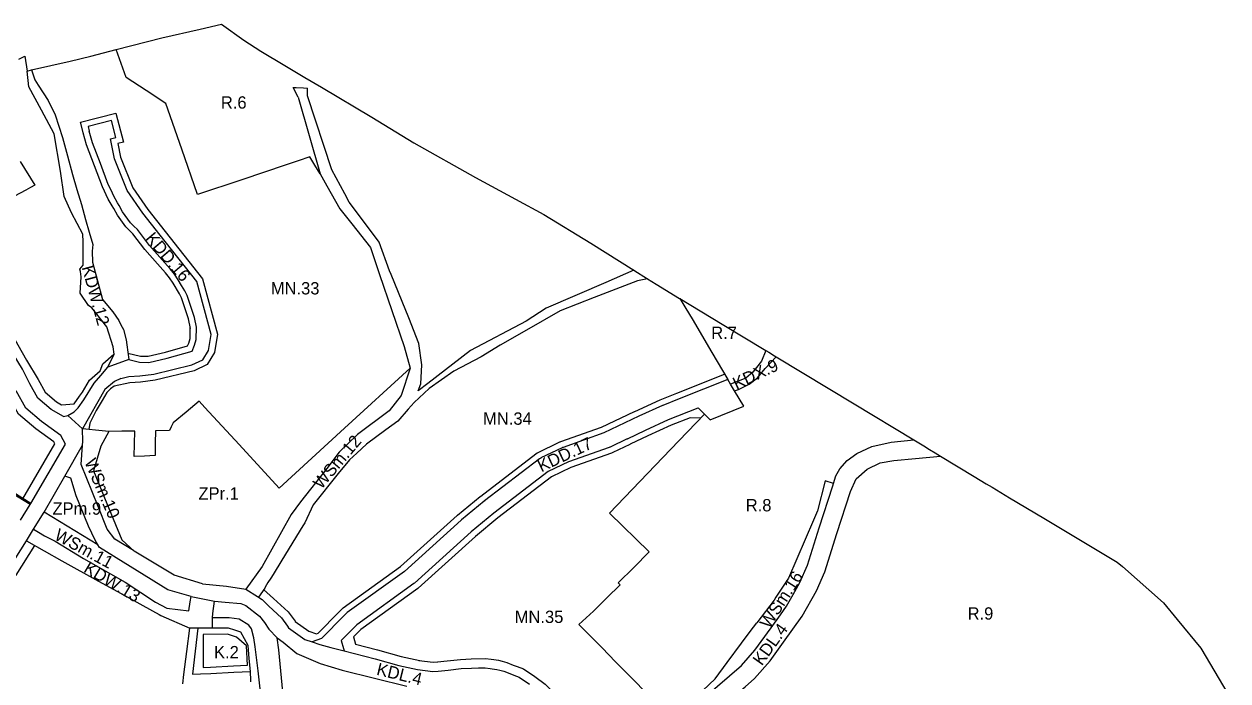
# Model space of a CAD drawing. Extents: x 7431080 to 7433370, y 5546450 to 5548428.
# Drawn here: x 7432562 to 7433342, y 5547508 to 5547934 of the extents above; entities that cross this region are included whole.
import ezdxf

# ---------------------------------------------------------------- set-up
doc = ezdxf.new("R2010")
doc.units = 0
for name, color, linetype in [('Linie Rozgraniczajace', 7, 'Continuous'), ('nieprzekraczalna linia zabudowy', 7, 'Continuous'), ('oznaczenia_przeznaczen', 7, 'Continuous')]:
    doc.layers.add(name, color=color, linetype=linetype)

msp = doc.modelspace()

# ---------------------------------------------------------------- linework, layer by layer
at = {"layer": 'Linie Rozgraniczajace'}
for p, q in [((7432736.74, 5547893.15), (7432738.64, 5547893.31)), ((7432739.88, 5547887.05), (7432736.74, 5547893.15)), ((7432738.64, 5547893.31), (7432743.31, 5547893.03)), ((7432743.31, 5547893.03), (7432745.96, 5547892.87)), ((7432745.83, 5547887.8), (7432745.96, 5547892.87)), ((7432630.14, 5547716.75), (7432616.64, 5547711.94)), ((7433018.29, 5547703.96), (7432986.81, 5547691.39)), ((7432600.23, 5547671.83), (7432590.53, 5547680.61)), ((7432670.6, 5547563.08), (7432685.71, 5547560.16)), ((7432674.84, 5547542.6), (7432669.79, 5547542.58)), ((7432830.69, 5547514.77), (7432837.12, 5547515.42)), ((7432837.12, 5547515.42), (7432845.5, 5547516.43)), ((7432845.5, 5547516.43), (7432852.26, 5547516.8)), ((7432852.26, 5547516.8), (7432856.77, 5547516.88)), ((7432856.77, 5547516.88), (7432861.06, 5547516.96)), ((7432861.06, 5547516.96), (7432864.23, 5547516.59)), ((7432864.23, 5547516.59), (7432865.68, 5547516.37)), ((7432865.68, 5547516.37), (7432868.53, 5547515.91)), ((7432868.53, 5547515.91), (7432870.64, 5547515.46)), ((7432870.64, 5547515.46), (7432873.14, 5547514.79)), ((7432873.14, 5547514.79), (7432876.99, 5547513.17)), ((7432876.99, 5547513.17), (7432879.7, 5547512.14)), ((7432709.13, 5547507.75), (7432709.11, 5547508.64)), ((7432879.7, 5547512.14), (7432883.07, 5547510.87)), ((7432883.07, 5547510.87), (7432889.86, 5547506.34)), ((7432982.62, 5547483.83), (7433010.04, 5547509.76))]:
    msp.add_line(p, q, dxfattribs=at)
for points in [[(7432558.92, 5547911.54), (7432562.86, 5547913.51), (7432564.19, 5547903.89), (7432567.09, 5547904.65), (7432592.1, 5547910.39), (7432605.56, 5547913.52), (7432622.02, 5547917.81), (7432651.51, 5547925.34), (7432676.39, 5547931.16), (7432690.27, 5547934.37), (7432704.62, 5547923.9), (7432715.72, 5547916.75), (7432731.3, 5547907.41), (7432744.28, 5547899.66), (7432755, 5547893.51), (7432787.72, 5547873.89), (7432814.91, 5547857.43), (7432854.84, 5547834.94), (7432880.76, 5547820.75), (7432899.09, 5547810.91), (7432929.43, 5547792.22), (7432957.36, 5547774.72), (7432966.22, 5547769.17), (7432971.79, 5547765.66), (7432987, 5547756.47), (7432987.09, 5547756.42), (7433014.57, 5547739.79), (7433042.93, 5547722.68), (7433044.83, 5547721.53), (7433048.58, 5547719.26), (7433049.72, 5547718.57), (7433100.18, 5547688.13), (7433138.81, 5547664.71), (7433145.3, 5547660.77), (7433148.91, 5547658.58), (7433152.72, 5547656.27), (7433156.12, 5547654.21), (7433178, 5547640.94), (7433185.69, 5547636.29), (7433189.55, 5547633.97), (7433200.87, 5547627.21), (7433223.05, 5547613.95), (7433248.93, 5547598.46), (7433270.56, 5547585.53), (7433273.96, 5547582.54), (7433300.55, 5547559.07), (7433309.47, 5547548.27), (7433324.78, 5547529.73), (7433342.34, 5547500)], [(7432654.21, 5547882.91), (7432641.32, 5547891.34), (7432628.43, 5547899.76), (7432625.23, 5547908.79), (7432622.02, 5547917.81)], [(7432587.74, 5547679.83), (7432590.53, 5547680.61), (7432594.68, 5547682.98), (7432597.33, 5547685.52), (7432601.04, 5547690.78), (7432607.78, 5547701.42), (7432611.99, 5547706.44), (7432616.64, 5547711.94), (7432620.59, 5547720.23), (7432620.03, 5547724.97), (7432615.88, 5547738.05), (7432606.1, 5547750.39), (7432604.04, 5547751.77), (7432598.65, 5547759.97), (7432599.38, 5547770.41), (7432598.77, 5547773.94), (7432598.49, 5547775.52), (7432600.47, 5547778.02), (7432600.49, 5547779.73), (7432600.67, 5547793.18), (7432600.35, 5547798.04), (7432592.99, 5547811.92), (7432588.3, 5547822.61), (7432585.93, 5547839.01), (7432581.86, 5547863.28), (7432573.58, 5547878.52), (7432565.31, 5547893.76), (7432564.19, 5547903.89)], [(7432567.09, 5547904.65), (7432569.35, 5547898.3), (7432571.48, 5547894.68), (7432577.93, 5547884.8), (7432582.51, 5547875.58), (7432584.86, 5547868.23), (7432587.2, 5547860.87), (7432590.45, 5547848.87), (7432593.69, 5547836.86), (7432596.55, 5547827.15), (7432599.41, 5547817.43), (7432602.14, 5547807.71), (7432604.45, 5547799.52), (7432606.75, 5547791.33), (7432606.38, 5547787.1), (7432606.57, 5547779.88), (7432609.83, 5547767.82), (7432613.08, 5547755.75), (7432619.9, 5547747.82), (7432623.76, 5547742.04), (7432625.08, 5547739.24), (7432626.74, 5547736.23), (7432628.47, 5547729.7), (7432628.86, 5547726.46), (7432630.14, 5547716.75)], [(7432817.74, 5547696.47), (7432819.36, 5547700.97), (7432820.05, 5547713.32), (7432818.1, 5547727.21), (7432811.58, 5547743.93), (7432807.25, 5547754.4), (7432800.12, 5547771.93), (7432799.17, 5547774.39), (7432792.35, 5547792.95), (7432782.92, 5547805.64), (7432772.97, 5547818.89), (7432770.07, 5547824.36), (7432761.74, 5547839.87), (7432745.83, 5547887.8)], [(7432754.11, 5547837.25), (7432750.78, 5547842.81), (7432747.46, 5547848.36), (7432739.83, 5547845.76), (7432732.21, 5547843.16), (7432703.48, 5547833.46), (7432674.76, 5547823.75), (7432664.48, 5547853.33), (7432654.21, 5547882.91)], [(7432739.88, 5547887.05), (7432754.11, 5547837.25), (7432758.46, 5547829.5), (7432766.95, 5547814.46), (7432774.75, 5547804.85), (7432786.7, 5547789.51), (7432792.59, 5547771.94), (7432808.57, 5547725.2), (7432812.52, 5547711.3), (7432806.56, 5547693.53), (7432798.81, 5547683.57), (7432778.38, 5547668.18), (7432766.46, 5547656.76), (7432758.44, 5547646.16), (7432741.43, 5547624.64), (7432735.43, 5547616.39), (7432716.57, 5547582.71), (7432705.87, 5547568.02)], [(7432624.93, 5547704.55), (7432630.26, 5547705.75), (7432637.36, 5547706.2), (7432646.41, 5547707.42), (7432671.05, 5547713.32), (7432678.08, 5547716.74), (7432681.89, 5547722.74), (7432683.45, 5547733.1), (7432674.28, 5547767.38), (7432650.53, 5547797.47), (7432639.31, 5547811.84), (7432629.16, 5547826.36), (7432620.96, 5547846.87), (7432618.25, 5547859.91), (7432621.75, 5547860.77), (7432618.83, 5547871.82), (7432603.74, 5547867.9), (7432604.52, 5547864.98)], [(7432587.74, 5547679.83), (7432579.8, 5547684.51), (7432571.24, 5547691.74), (7432566.01, 5547701.14), (7432561.27, 5547710.64), (7432548.45, 5547731.47), (7432545.14, 5547735.9), (7432530.25, 5547751.38), (7432524.17, 5547756.85), (7432520.51, 5547760.07), (7432515.88, 5547764.35), (7432503.45, 5547774.93), (7432499.46, 5547778.72), (7432489.5, 5547786.69), (7432489.3, 5547786.84), (7432475.05, 5547797.72), (7432454.78, 5547813.38), (7432447.21, 5547819.23), (7432439.7, 5547823.93), (7432421.26, 5547834.62), (7432399.96, 5547844.46), (7432384.82, 5547857.78), (7432377.84, 5547863.93), (7432370.3, 5547871.33)], [(7432673.98, 5547737.73), (7432672.72, 5547744.17), (7432670.38, 5547751.27), (7432668.04, 5547758.37), (7432666.49, 5547761.43), (7432664.36, 5547764.94), (7432662.22, 5547768.44), (7432659.77, 5547772.26), (7432656.86, 5547775.59), (7432651.69, 5547781.49), (7432643.6, 5547790.71), (7432635.68, 5547801.09), (7432633.48, 5547803.26), (7432631.28, 5547805.43), (7432626.16, 5547812.61), (7432623.84, 5547816.7), (7432622.88, 5547818.38), (7432620.42, 5547822.71), (7432618.61, 5547826.58), (7432616.79, 5547830.44), (7432611.7, 5547843.85), (7432606.6, 5547857.26), (7432604.52, 5547864.98)], [(7432559.83, 5547845.32), (7432569.26, 5547829.92), (7432566.38, 5547828.34), (7432563.49, 5547826.76), (7432552.4, 5547820.92)], [(7432566.65, 5547623.4), (7432513.9, 5547656.51), (7432486.02, 5547678.29), (7432481.13, 5547684.37), (7432474.43, 5547732.1), (7432469.33, 5547782.86), (7432468.91, 5547787.5), (7432468.74, 5547789.08)], [(7432957.36, 5547774.72), (7432939.2, 5547766.71), (7432900.56, 5547750.05), (7432887.6, 5547741.65), (7432851.64, 5547722.65), (7432823.9, 5547701.27), (7432817.74, 5547696.47)], [(7432966.22, 5547769.17), (7432959.85, 5547767.93), (7432931.78, 5547757.04), (7432909.64, 5547748.34), (7432887.78, 5547735.82), (7432870.68, 5547726.18), (7432858.52, 5547718.67), (7432840.77, 5547709.35), (7432824.81, 5547698.01), (7432815.04, 5547688.97), (7432811.25, 5547684.64), (7432804.57, 5547676.83), (7432796.71, 5547671.16), (7432784.12, 5547662.02), (7432777.96, 5547656.17), (7432773.13, 5547651.86), (7432765.87, 5547642.88), (7432749.58, 5547622.58), (7432744.16, 5547610.86), (7432742.85, 5547608.91), (7432729.33, 5547586.74)], [(7432987.09, 5547756.42), (7432991.04, 5547749.85), (7432995.09, 5547743.23), (7433007.94, 5547721.49), (7433018.29, 5547703.96)], [(7432630.14, 5547716.75), (7432637.09, 5547715.09), (7432643.03, 5547714.9), (7432654.98, 5547717.64), (7432671.16, 5547722.35), (7432672.74, 5547726.06), (7432673.8, 5547729.78), (7432673.98, 5547737.73)], [(7433042.93, 5547722.68), (7433040.02, 5547715.79), (7433034.45, 5547708.55), (7433029.95, 5547704.84), (7433020.12, 5547700.87)], [(7433022.67, 5547696.57), (7433025.11, 5547697.42), (7433032.07, 5547700.79), (7433037.47, 5547704.95), (7433042.39, 5547711.11), (7433049.72, 5547718.57)], [(7432566.3, 5547622.84), (7432525.41, 5547647.78), (7432490.91, 5547668.16), (7432485.92, 5547672.31), (7432482.52, 5547675.32), (7432477.4, 5547681.69), (7432474.91, 5547688.4), (7432474.86, 5547689.68), (7432472.92, 5547712.69)], [(7432812.52, 5547711.3), (7432770, 5547672.38), (7432727.49, 5547633.46), (7432701.57, 5547661.64), (7432679.44, 5547685.68), (7432675.65, 5547689.82)], [(7432624.93, 5547704.55), (7432620.95, 5547702.5), (7432614.55, 5547697.35), (7432600.23, 5547671.83)], [(7432998.98, 5547685.47), (7433003.17, 5547681.37), (7433006.78, 5547677.83), (7433028.61, 5547686.55), (7433022.67, 5547696.57), (7433020.12, 5547700.87), (7433018.29, 5547703.96)], [(7432559.96, 5547612.73), (7432566.3, 5547622.84), (7432566.65, 5547623.4), (7432589.03, 5547662.02), (7432586.19, 5547667.58), (7432573.64, 5547676.62), (7432563.38, 5547685.29), (7432557.16, 5547696.48)], [(7432675.65, 5547689.82), (7432667.23, 5547682.76), (7432658.81, 5547675.71), (7432657.65, 5547673.25), (7432656.48, 5547670.79), (7432647.38, 5547670.66), (7432647.28, 5547662.58), (7432647.18, 5547654.51), (7432640.4, 5547654.24), (7432633.62, 5547653.98), (7432633.8, 5547662.22), (7432633.98, 5547670.46), (7432625.62, 5547670.34), (7432617.25, 5547670.22), (7432614.67, 5547665.48), (7432612.08, 5547660.74)], [(7432986.81, 5547691.39), (7432976.1, 5547687.13), (7432976, 5547687.05), (7432975.86, 5547687.03), (7432960.65, 5547680.06), (7432960.63, 5547680.03), (7432960.59, 5547680.02), (7432937.91, 5547669.21), (7432911.53, 5547659.87), (7432911.09, 5547659.7), (7432911.06, 5547659.68), (7432911.03, 5547659.67), (7432897.13, 5547653.01), (7432897.08, 5547652.97), (7432896.25, 5547652.47), (7432860.63, 5547625.15), (7432860.54, 5547625.08), (7432860.49, 5547625.03), (7432845.63, 5547612.78), (7432845.5, 5547612.67), (7432845.45, 5547612.63), (7432808.82, 5547579.48), (7432771.67, 5547552.78), (7432771.15, 5547552.31), (7432771.05, 5547552.23), (7432767.29, 5547548.44)], [(7432953.13, 5547665.39), (7432953.25, 5547665.45), (7432964.86, 5547670.98), (7432979.92, 5547677.89), (7432998.98, 5547685.47)], [(7433003.17, 5547681.37), (7432981.17, 5547658.43), (7432941.67, 5547617.28), (7432967.24, 5547592.06), (7432957.29, 5547582), (7432947.33, 5547571.93), (7432948.5, 5547570.78), (7432939.88, 5547562.21), (7432931.25, 5547553.63)], [(7432551.75, 5547580.08), (7432563.79, 5547599.35), (7432568.39, 5547606.8), (7432575.34, 5547617.95), (7432588.63, 5547641.16), (7432600.18, 5547661.32), (7432600.34, 5547663.69), (7432600.23, 5547671.83)], [(7432617.25, 5547670.22), (7432612.84, 5547670.69), (7432600.23, 5547671.83)], [(7432677.89, 5547571.45), (7432659.51, 5547577.06), (7432633.67, 5547592.6), (7432633.12, 5547592.94), (7432621.09, 5547600.37), (7432616.18, 5547606.93), (7432610.33, 5547621.43), (7432599.33, 5547648.67), (7432600.18, 5547661.32)], [(7432953.13, 5547665.39), (7432941.97, 5547660.06), (7432941.94, 5547660.06), (7432941.91, 5547660.04), (7432941.49, 5547659.86), (7432915.11, 5547650.54), (7432901.92, 5547644.22), (7432866.78, 5547617.26), (7432852.08, 5547605.14), (7432815.32, 5547571.88), (7432815.17, 5547571.79), (7432814.89, 5547571.53), (7432777.86, 5547544.9)], [(7433086.41, 5547634.97), (7433086.87, 5547636.5), (7433088.33, 5547641.32), (7433090.8, 5547645.93), (7433095.72, 5547651.3), (7433101.79, 5547655.93), (7433111.56, 5547660.48), (7433124.14, 5547663.21), (7433138.81, 5547664.71)], [(7432612.08, 5547660.74), (7432607.28, 5547644.64), (7432612.58, 5547631.4), (7432614.3, 5547627.11), (7432625.69, 5547599.85), (7432633.67, 5547592.6)], [(7433097.82, 5547631.25), (7433101.5, 5547639.44), (7433108.52, 5547645.83), (7433117.1, 5547649.82), (7433125.77, 5547651.31), (7433139.9, 5547652.75), (7433156.12, 5547654.21)], [(7432654.83, 5547555.59), (7432669, 5547553.92), (7432669.83, 5547559.63), (7432670.6, 5547563.08), (7432655.51, 5547567.49), (7432611.07, 5547594.96), (7432610.12, 5547596.61), (7432608.37, 5547599.66), (7432606.2, 5547604.27), (7432604.02, 5547608.88), (7432595.95, 5547628.41), (7432592.57, 5547639.93), (7432588.63, 5547641.16)], [(7433086.87, 5547636.5), (7433081.33, 5547638.22), (7433076.32, 5547618.65), (7433073.82, 5547612.63), (7433057.59, 5547575.01), (7433049.48, 5547562.81), (7433048.22, 5547560.72), (7433037.14, 5547546.09)], [(7433045.71, 5547521.4), (7433054.31, 5547533.54), (7433066.41, 5547550.51), (7433075.77, 5547566.85), (7433081.25, 5547579.26), (7433088.94, 5547603.98), (7433097.82, 5547631.25)], [(7433046.28, 5547542.85), (7433052.48, 5547551.32), (7433056.21, 5547556.85), (7433060.63, 5547564.56), (7433065.05, 5547572.27), (7433070, 5547583.48), (7433077.5, 5547607.62), (7433086.41, 5547634.97)], [(7432610.12, 5547596.61), (7432595.11, 5547605.82), (7432575.34, 5547617.95)], [(7432568.39, 5547606.8), (7432571.65, 5547604.85), (7432575.42, 5547602.59), (7432582.47, 5547598.95), (7432600.76, 5547587.84), (7432627.88, 5547572.37), (7432647.43, 5547559.49), (7432654.83, 5547555.59)], [(7432563.79, 5547599.35), (7432586.76, 5547586.4), (7432610.44, 5547573.04), (7432625.15, 5547565.02), (7432639.21, 5547557.36), (7432649.81, 5547551.57), (7432650.98, 5547550.94), (7432669.79, 5547542.58)], [(7432729.33, 5547586.74), (7432723.6, 5547577.51), (7432722.2, 5547575.03), (7432720.3, 5547572.15), (7432718.45, 5547569.16), (7432718.18, 5547568.51), (7432714.14, 5547562.81)], [(7432677.89, 5547571.45), (7432693.51, 5547569.83), (7432705.87, 5547568.02), (7432713.53, 5547563.22), (7432714.14, 5547562.81), (7432716.58, 5547561.18), (7432720.96, 5547556.96), (7432729.1, 5547549.25), (7432733.01, 5547543.87), (7432733.64, 5547542.83), (7432744.14, 5547535.37), (7432749.02, 5547533.72), (7432753.91, 5547532.07), (7432761.15, 5547530.19), (7432769.63, 5547527.99)], [(7432684.27, 5547549.31), (7432684.63, 5547552.22), (7432685.71, 5547560.16), (7432692.57, 5547559.49), (7432702.74, 5547558.65), (7432706.07, 5547557.26), (7432714.86, 5547550.38), (7432718.05, 5547546.39), (7432720.97, 5547541.9), (7432726.36, 5547536.37), (7432730.08, 5547533.53), (7432738.98, 5547526.29), (7432754.14, 5547519.63), (7432768.49, 5547515.46), (7432810.21, 5547505.05)], [(7432928.37, 5547538.37), (7432921.84, 5547545.04), (7432926.55, 5547549.34), (7432931.25, 5547553.63)], [(7432713.86, 5547514.97), (7432711.97, 5547530.56), (7432711.07, 5547536.35), (7432709.64, 5547542.25), (7432707.83, 5547544.56), (7432701.72, 5547548.42), (7432695.2, 5547549.34), (7432684.27, 5547549.31)], [(7432684.47, 5547542.64), (7432684.27, 5547549.31)], [(7432767.29, 5547548.44), (7432757.48, 5547538.34), (7432755.05, 5547535.84), (7432749.02, 5547533.72)], [(7432777.86, 5547544.9), (7432767.74, 5547534.59), (7432769.19, 5547529.52), (7432769.63, 5547527.99)], [(7433010.04, 5547509.76), (7433017.9, 5547520.3), (7433027.26, 5547532.85), (7433032.84, 5547540.49), (7433037.14, 5547546.09)], [(7432665.2, 5547506.49), (7432665.75, 5547512.53), (7432667.77, 5547527.55), (7432669.79, 5547542.58)], [(7432674.84, 5547542.6), (7432671.34, 5547512.9), (7432676.55, 5547513.06), (7432683.26, 5547513.35), (7432698.15, 5547514.11), (7432708.95, 5547514.64)], [(7432709.11, 5547508.64), (7432708.95, 5547514.64), (7432708.21, 5547523.02), (7432707.47, 5547531.4), (7432705.09, 5547535.71), (7432702.72, 5547540.01), (7432698.76, 5547541.35), (7432694.8, 5547542.69), (7432684.47, 5547542.64), (7432682.29, 5547542.63), (7432674.84, 5547542.6)], [(7432774.33, 5547211.33), (7432766.65, 5547209.56), (7432764.79, 5547209.37), (7432762.43, 5547225.59), (7432755.48, 5547271.31), (7432752.81, 5547291.41), (7432749.09, 5547319.44), (7432742.62, 5547372.72), (7432736.91, 5547420.37), (7432733.47, 5547460.86), (7432730.03, 5547501.34), (7432727.43, 5547528.51), (7432726.36, 5547536.37)], [(7432928.37, 5547538.37), (7432936.78, 5547529.78), (7432945.54, 5547520.83), (7432954.3, 5547511.88), (7432958.8, 5547507.42), (7432963.3, 5547502.97), (7432972.96, 5547493.4), (7432982.62, 5547483.83)], [(7432965.39, 5547468.19), (7432969.04, 5547470.51), (7432977.24, 5547476.44), (7432997.87, 5547493.15), (7433003.78, 5547498.29), (7433027.14, 5547518.47), (7433035.83, 5547528.39), (7433046.28, 5547542.85)], [(7432769.63, 5547527.99), (7432789.76, 5547522.75), (7432805.15, 5547518.53), (7432817.28, 5547515.74)], [(7432971.88, 5547457.4), (7432975.45, 5547459.56), (7432981.41, 5547463.82), (7432984.03, 5547465.69), (7433005.69, 5547484.04), (7433011.64, 5547489.22), (7433029.48, 5547504.64), (7433035.61, 5547509.93), (7433045.71, 5547521.4)], [(7432716.06, 5547497.22), (7432715.66, 5547499.62), (7432714.76, 5547507.29), (7432713.86, 5547514.97)], [(7432817.28, 5547515.74), (7432827.04, 5547514.61), (7432830.69, 5547514.77)]]:
    msp.add_lwpolyline(points, dxfattribs=at)
at = {"layer": 'nieprzekraczalna linia zabudowy'}
for p, q in [((7432630.16, 5547716.72), (7432630.15, 5547716.72)), ((7432678.42, 5547538.62), (7432678.42, 5547517.14))]:
    msp.add_line(p, q, dxfattribs=at)
for points in [[(7432600.65, 5547863.95), (7432598.84, 5547870.76), (7432621.68, 5547876.69), (7432626.66, 5547857.86), (7432622.95, 5547856.95), (7432624.8, 5547848.03), (7432632.7, 5547828.27), (7432642.53, 5547814.22), (7432653.68, 5547799.94), (7432677.93, 5547769.21), (7432687.53, 5547733.33), (7432685.72, 5547721.31), (7432680.86, 5547713.63), (7432672.41, 5547709.53), (7432647.15, 5547703.48), (7432637.76, 5547702.21), (7432630.83, 5547701.77), (7432620.65, 5547699.49)], [(7432670.05, 5547736.96), (7432668.84, 5547743.16), (7432664.34, 5547756.83), (7432662.99, 5547759.48), (7432658.83, 5547766.32), (7432656.56, 5547769.85), (7432653.85, 5547772.95), (7432648.68, 5547778.85), (7432640.5, 5547788.18), (7432632.67, 5547798.44), (7432628.22, 5547802.83), (7432622.78, 5547810.46), (7432620.36, 5547814.72), (7432619.4, 5547816.4), (7432616.87, 5547820.87), (7432613.1, 5547828.88), (7432602.79, 5547856.03), (7432600.66, 5547863.94)], [(7432561.56, 5547626.59), (7432582.2, 5547662.2), (7432581.51, 5547663.56), (7432569.94, 5547671.89), (7432558.68, 5547681.42), (7432551.85, 5547693.68), (7432541.98, 5547713.5), (7432534.91, 5547724.03), (7432532.16, 5547727.33), (7432523.01, 5547736.36), (7432469.56, 5547780.61)], [(7432553.42, 5547734.84), (7432563.88, 5547716.39), (7432571.32, 5547703.94), (7432575.95, 5547695.62), (7432583.28, 5547689.42), (7432586.5, 5547687.53), (7432594.64, 5547688.19)], [(7432629.58, 5547721), (7432637.62, 5547719.07), (7432642.64, 5547718.91), (7432653.97, 5547721.51), (7432668.22, 5547725.66), (7432668.97, 5547727.4), (7432669.81, 5547730.38), (7432669.98, 5547737.82)], [(7432594.64, 5547688.19), (7432598.09, 5547693.01), (7432600.14, 5547695.68), (7432604.63, 5547703.41), (7432611.63, 5547709.4), (7432613.25, 5547714.13), (7432620.41, 5547720.26)], [(7432751.82, 5547538.95), (7432752.84, 5547539.3), (7432754.61, 5547541.13), (7432764.44, 5547551.24), (7432768.37, 5547555.21), (7432768.56, 5547555.36), (7432769.15, 5547555.9), (7432806.3, 5547582.6), (7432842.86, 5547615.68), (7432842.96, 5547615.76), (7432843.07, 5547615.85), (7432857.8, 5547627.99), (7432857.89, 5547628.08), (7432858.18, 5547628.32), (7432893.99, 5547655.78), (7432894.79, 5547656.26), (7432894.99, 5547656.42), (7432909.53, 5547663.39), (7432909.55, 5547663.39), (7432910.14, 5547663.62), (7432936.38, 5547672.91), (7432957.92, 5547683.18), (7432957.95, 5547683.22), (7432974.36, 5547690.74), (7432985.33, 5547695.11), (7433016.24, 5547707.45)], [(7432620.65, 5547699.49), (7432618.37, 5547697.84), (7432616, 5547695.56), (7432612.92, 5547690.35), (7432609.06, 5547683.87), (7432604.79, 5547675.5), (7432604.22, 5547671.47)], [(7433000.71, 5547678.8), (7432993.84, 5547679.12), (7432981.49, 5547674.21), (7432966.55, 5547667.36), (7432955, 5547661.86), (7432954.89, 5547661.8), (7432943.85, 5547656.52), (7432943.82, 5547656.51), (7432942.95, 5547656.13), (7432916.64, 5547646.84), (7432904.02, 5547640.79), (7432869.27, 5547614.13), (7432854.7, 5547602.11), (7432817.71, 5547568.65), (7432817.59, 5547568.57), (7432817.43, 5547568.43), (7432780.47, 5547541.85), (7432775.75, 5547537.04), (7432777.07, 5547532.25)], [(7432568.97, 5547596.32), (7432556.92, 5547577.03), (7432543.23, 5547552.53), (7432534.38, 5547536.04), (7432531.68, 5547530.87)], [(7432717.48, 5547567.61), (7432719.67, 5547565.74), (7432723.91, 5547561.88), (7432733.51, 5547553.13), (7432737.89, 5547547.11), (7432738.02, 5547546.9), (7432746.83, 5547540.64), (7432751.82, 5547538.95)], [(7432707.03, 5547518.55), (7432706.43, 5547531.19), (7432699.97, 5547536.72), (7432694.15, 5547538.69), (7432678.42, 5547538.62)], [(7432777.07, 5547532.25), (7432791.31, 5547528.55), (7432806.62, 5547524.35), (7432818.62, 5547521.59)], [(7432817.97, 5547521.7), (7432827.26, 5547520.62), (7432830.43, 5547520.76)], [(7432830.08, 5547520.74), (7432836.46, 5547521.38), (7432844.98, 5547522.41), (7432852.04, 5547522.8), (7432861.36, 5547522.97), (7432865.02, 5547522.54), (7432866.6, 5547522.3), (7432869.63, 5547521.81), (7432872.05, 5547521.29), (7432875.09, 5547520.47), (7432879.22, 5547518.74), (7432881.83, 5547517.75), (7432885.83, 5547516.24), (7432893.32, 5547511.24), (7432899.83, 5547506.38), (7432909.72, 5547496.6)], [(7432678.42, 5547517.14), (7432683.07, 5547517.35), (7432697.95, 5547518.11), (7432707.03, 5547518.55)]]:
    msp.add_lwpolyline(points, dxfattribs=at)

# ---------------------------------------------------------------- texts
at = {"layer": 'oznaczenia_przeznaczen'}
for s, p in [('R.6', (7432689.8, 5547879.52)), ('MN.33', (7432722.17, 5547759.04)), ('R.7', (7433007.55, 5547730.14)), ('MN.34', (7432859.71, 5547674.55)), ('ZPr.1', (7432675.3, 5547626.01)), ('ZPm.9', (7432580.69, 5547616.2)), ('R.8', (7433029.92, 5547618.38)), ('MN.35', (7432880.21, 5547545.99)), ('R.9', (7433173.67, 5547548.16)), ('K.2', (7432685.37, 5547523.08))]:
    msp.add_text(s, height=8, dxfattribs=at).set_placement(p)
for s, rotation, p in [('KDD.16', 310.29333, (7432640.46, 5547795.16)), ('KDW.12', 285.29496, (7432599.59, 5547776.64)), ('KDX.9', 25.24176, (7433023.88, 5547697.13)), ('WSm.12', 49.64826, (7432754.88, 5547632.27)), ('KDD.17', 25.24176, (7432897.41, 5547643.64)), ('WSm.10', 293.20605, (7432601.24, 5547650.54)), ('WSm.11', 331.42985, (7432581.27, 5547600.57)), ('KDW.13', 329.07652, (7432600.33, 5547579.47)), ('WSm.16', 57.21096, (7433045.17, 5547541.82)), ('KDL.4', 54.39848, (7433040.34, 5547517.83)), ('KDL.4', 346.29596, (7432790.17, 5547512.53))]:
    msp.add_text(s, height=8, rotation=rotation, dxfattribs=at).set_placement(p)

doc.saveas('drawing.dxf')
